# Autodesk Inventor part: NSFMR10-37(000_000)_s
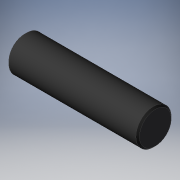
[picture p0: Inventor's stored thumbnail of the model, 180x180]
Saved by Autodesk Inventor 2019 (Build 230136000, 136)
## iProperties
Created: 2022-11
Part Number: NSFMR10-37(000_000)_s
Material: Generic
Catalog Web Link: www.cadenas.de
Description: NSFMR, SFMR, PSFMR, SSFMR, SSSFMR, NSFHR, SFHR, PSFHR, PPSFHR SSFHR, SSSFHR, NSFR, SFR, PSFR, PPSFR, SSFR, SSSFR, HFR, PHFR_shaft-Rotary Shafts - Straight -
Vendor: MISUMI
Document SubType Name: Modeling
Designer: psAdmin
Manufacturer: MISUMI
Mass: 2.89838 g
Surface Area: 13.0042 cm^2
Volume: 2.89838 cm^3
Density: 1 g/cm^3
Appearance: PSOLRGB-175-175-175
Category: PARTsolutions
Company: MISUMI
Title: NSFMR10-37
Author: Cadenas PARTsolutions
Comments: Rotary Shafts - Straight -
PSOL_IDENT_0: {$CADENAS_DATA/23d-libs/misumi/metric/11_rotary_shafts/11_components/psfr/psfr.prj},560 {VTYP=3D},{N
PSOL_IDENT_1: B=NSFMR10-37(000_000)_s},{LINA=NSFMR10-37},{NN=NSFMR, SFMR, PSFMR, SSFMR, SSSFMR, NSFHR, SFHR, PSFHR
PSOL_IDENT_2: , PPSFHR SSFHR, SSSFHR, NSFR, SFR, PSFR, PPSFR, SSFR, SSSFR, HFR, PHFR_shaft},{DATE=21.04.2022 07:40
PSOL_IDENT_3: :10},{GEOMDATE=27.07.2021 07:07:13},{VERSION=},{LINEID=30},{WBVAR=TS,MAT,ST,ALT1,L,ALT2,KC,A,WKC,C,K
PSOL_IDENT_4: ,E,KZ,Z,ALT3,FC,GALT3,WFC,J,WALT3,V,ALT4,SFC,SG,AG,ALT10,KWC,ALT11,WC,ALT6,TA,TB,ALT5,UC,ALT7,SC,ALT
PSOL_IDENT_5: 32,CD,ALT34,TCJ,WTCJ,XT,HCJ,WHCJ,XH},{WBNUMERIC=L,KC,A,WKC,C,K,E,KZ,Z,FC,GALT3,WFC,J,WALT3,V,SFC,SG,
PSOL_IDENT_6: AG,KWC,WC,TA,TB,UC,SC,TCJ,WTCJ,XT,HCJ,WHCJ,XH}  {NB=NSFMR10-37(000_000)_s},{LINA=NSFMR10-37},{KT=DUM
PSOL_IDENT_7: MY},{PN=NSFMR10-37},{TYPE=NSFMR},{TS=M},{TSALG= 'M','h9 (Cold-drawn)','H','h7 (Ground)','','g6 (Grou
PSOL_IDENT_8: nd)' },{MAT=S45C},{MATALG= 'S45C','S45C Equivalent', 'SUS304','304 Stainless Steel' },{ST=},{STALG= ''
PSOL_IDENT_9: ,'-','BO','Black Oxide', 'ENP','Electroless Nickel Plating' },{D=10.0},{ALT1=},{L=37.0},{LALG=[15:80
PSOL_IDENT_10: 0/0.1]},{LMIN=15},{LMAX=800},{NOTE=Not Applicable},{ALT2=},{ALT2ALG= '', 'w/o Key Grooves','KC','wit
PSOL_IDENT_11: h KC (Key Groove)','WKC','with WKC (Two Key Grooves)','KCWKC','with KC + WKC (Three Key Grooves)','K
PSOL_IDENT_12: Z','with KC + WKC + KZ (Four Key Grooves)' },{ALT2PN=},{KC=0.0},{KCALG=[0]},{KCMIN=0},{KCMAX=0},{A=0
PSOL_IDENT_13: .0},{AALG=[0]},{AMIN=3},{AMAX=0},{WKC=0.0},{WKCALG=[0]},{WKCMIN=0},{WKCMAX=0},{C=0.0},{CALG=[0]},{CM
PSOL_IDENT_14: IN=3},{CMAX=0},{K=0.0},{KALG=[0]},{KMIN=0},{KMAX=32},{E=0.0},{EALG=[0]},{EMIN=3},{EMAX=35},{KZ=0.0},
PSOL_IDENT_15: {KZALG=[0]},{KZMIN=39},{KZMAX=34},{Z=0.0},{ZALG=[0]},{ZMIN=3},{ZMAX=37},{CIFKC=1},{CIFWKC=1},{CIFK=1
PSOL_IDENT_16: },{CIFKZ=2},{PCUT3D=0.000},{QCUT3D=0},{BB=3},{BBALT2=3},{TT=1.8},{TTALT2=1.8},{ALT3=},{ALT3ALG= '', '
PSOL_IDENT_17: w/o Set Screw Flat','FC','with FC (Adds a Set Screw Flat)','WFC','with WFC (Adds Two Set Screw Flats
PSOL_IDENT_18: )','FCWFC','with FC + WFC (Adds Three Set Screw Flats)' },{ALT3PN=},{FC=0},{FCALG=[0]},{FCMIN=0},{FC
PSOL_IDENT_19: MAX=36},{GALT3=0},{GALT3ALG=[0]},{GALT3MIN=1},{GALT3MAX=37},{GALT3MAX2=31},{GALT3MAX3=34},{WFC=0},{W
PSOL_IDENT_20: FCALG=[0]},{WFCMIN=0},{WFCMIN2=2},{WFCMAX=33},{WFCMAX2=-3},{WFCMAX3=-4},{J=0},{JALG=[0]},{JMIN=1},{J
PSOL_IDENT_21: MAX=34},{JMAX2=-2},{JMAX3=-5},{WALT3=0},{WALT3ALG=[0]},{WALT3MIN=0},{WALT3MIN2=39},{WALT3MAX=34},{WA
PSOL_IDENT_22: LT3MAX2=34},{WALT3MAX3=34},{V=0},{VALG=[0]},{VMIN=1},{VMAX=35},{VMAX2=35},{VMAX3=35},{CIFFC=0},{ALT4=
PSOL_IDENT_23: },{ALT4ALG= '', 'w/o SFC (2 Set Screw Flats (Angle Specified))', 'SFC'  , 'with SFC (2 Set Screw Fla
PSOL_IDENT_24: ts (Angle Specified))'},{ALT4PN=},{SFC=0},{SFCALG=[0]},{SFCMIN=0},{SFCMAX=36},{SG=0},{SGALG=[0]},{SG
PSOL_IDENT_25: MIN=1},{SGMAX=37},{AG=0},{AGALG=[0]},{H=0.0},{CIFSFC=0},{ALT10=},{ALT10ALG= '', 'w/o KWC (2 Set Scre
PSOL_IDENT_26: w Flats at both ends)', 'KWC', 'with KWC (2 Set Screw Flats at both ends)' },{ALT10PN=},{KWC=0},{KWC
PSOL_IDENT_27: ALG=[0]},{KWCMIN=1},{KWCMAX=17.5},{WALT10=8},{ALT11=},{ALT11ALG= '','Not applicable' },{ALT11PN=},{W
PSOL_IDENT_28: C=0.0},{WCALG=[0]},{ALT6=},{ALT6ALG= '','w/o Retaining Ring Groove','TA','with TA (Retaining Ring Gr
PSOL_IDENT_29: oove)','TB','with TB (Retaining Ring Groove)','TATB','with TA + TB (Two Retaining Ring Grooves)' },{
PSOL_IDENT_30: ALT6PN=},{TA=0.0},{TAALG=[0]},{TAMIN=2},{TAMAX=0},{TB=0.0},{TBALG=[0]},{TBMIN=2},{TBMAX=0},{DDALT6=0
PSOL_IDENT_31: .0},{MM=0.00},{ALT5=},{ALT5ALG= '', 'w/o UC (Slit Cam Groove)', 'UC', 'with UC (Slit Cam Groove)'},{
PSOL_IDENT_32: ALT5PN=},{UC=0},{UCALG=[0]},{UCMIN=1},{UCMAX=31},{DDALT5=0},{LL1=0},{ALT7=},{ALT7ALG= '', 'w/o SC (W
PSOL_IDENT_33: rench Flats)', 'SC', 'with SC (Wrench Flats)'},{ALT7PN=},{SC=0},{SCALG=[0]},{SCMIN=0},{SCMAX=29},{WA
PSOL_IDENT_34: LT7=0},{LL2=0},{LL2ALG=8},{CIFSC=0},{ALT32=},{ALT32ALG=  '','w/o CD (Changes Part D Chamfering)','-C
PSOL_IDENT_35: D', 'with CD (Changes Part D Chamfering)' },{ALT32PN=},{CD=},{CDALG= '','N/A' },{CD3D=0.5},{CIF32=0}
PSOL_IDENT_36: ,{CIF320=0},{CIFTA=0},{CIFTB=0},{ERRORPN=},{ERRORALT23=OK},{ERRORALT24=OK},{ERRORALT25=OK},{ERRORALT
PSOL_IDENT_37: 26=OK},{ERRORALT27=OK},{ERRORALT210=OK},{ERRORALT34=OK},{ERRORALT35=OK},{ERRORALT36=OK},{ERRORALT37=
PSOL_IDENT_38: OK},{ERRORALT310=OK},{ERRORALT45=OK},{ERRORALT46=OK},{ERRORALT47=OK},{ERRORALT410=OK},{ERRORALT56=OK
PSOL_IDENT_39: },{ERRORALT57=OK},{ERRORALT510=OK},{ERRORALT610=OK},{ERRORALT75=OK},{ERRORALT76=OK},{ERRORALT710=OK}
PSOL_IDENT_40: ,{ALT34=},{ALT34ALG= '','Not applicable'},{TCJ=0},{WTCJ=0},{XT=0},{TM=4},{TCJALG=[0]},{TCJMIN=0.000}
PSOL_IDENT_41: ,{TCJMAX=15.000},{TCJMAX1=15.000},{HCJ=0},{WHCJ=0},{XH=0},{HP=4},{HCJALG=[0]},{HCJMIN=0.000},{HCJMAX=
PSOL_IDENT_42: 15.000},{HCJMAX1=15.000},{LCJ=0},{LMINX=15},{XCJMIN=4.000},{XALG=[0]},{XCJMAX=15.000},{WHCJMIN=0.000
PSOL_IDENT_43: },{WTCJMIN=0.000},{WTCJALG=[0]},{WHCJALG=[0]},{XHCJMIN=4.000},{XHALG=[0]}
NB: NSFMR10-37(000_000)_s
NN: NSFMR, SFMR, PSFMR, SSFMR, SSSFMR, NSFHR, SFHR, PSFHR, PPSFHR SSFHR, SSSFHR, NSFR, SFR, PSFR, PPSFR, SSFR, SSSFR, HFR, PHFR_shaft
NT: Rotary Shafts - Straight -
NBSYN: $PN.($ALT34.$TCJ.$WTCJ.$XT._$HCJ.$WHCJ.$XH.)_s
LINA: NSFMR10-37
CATALOG: Misumi
PN: NSFMR10-37
TS: h9 (Cold-drawn)
MAT: S45C Equivalent
ST: -
D: 10
ALT1: w/o LKC (Changes L Tolerance)
L: 37
ALT2: w/o Key Grooves
KC: 0
A: 0
WKC: 0
C: 0
K: 0
E: 0
KZ: 0
Z: 0
ALT3: w/o Set Screw Flat
FC: 0
GALT3: 0
WFC: 0
J: 0
WALT3: 0
V: 0
ALT4: w/o SFC (2 Set Screw Flats (Angle Specified))
SFC: 0
SG: 0
AG: 0
H: 0
ALT10: w/o KWC (2 Set Screw Flats at both ends)
KWC: 0
ALT11: Not applicable
WC: 0
ALT6: w/o Retaining Ring Groove
TA: 0
TB: 0
DDALT6: 0
MM: 0
ALT5: w/o UC (Slit Cam Groove)
UC: 0
DDALT5: 0
LL1: 0
ALT7: w/o SC (Wrench Flats)
SC: 0
WALT7: 0
LL2: 0
ALT32: w/o CD (Changes Part D Chamfering)
CD: N/A
ALT34: Not applicable
TCJ: 0
WTCJ: 0
XT: 0
HCJ: 0
WHCJ: 0
XH: 0
SUPPLIER: MISUMI
ARTICLENO: NSFMR10-37(000_000)_s
BOMINFO: NSFMR10-37
CREATOR: CADENAS GmbH
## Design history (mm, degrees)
sketch "Sketch_1"
  geometry: L1 (37, 0)-(0, 0); L2 (0, 0)-(0, 4.5); L3 (0, 4.5)-(0.5, 5); L4 (0.5, 5)-(36.5, 5); L5 (36.5, 5)-(37, 4.5); L6 (37, 4.5)-(37, 0); L7 (37, 0)-(0, 0)
  constraints: 14 end point
revolve "Revolution1" sketch "Sketch_1" stored, may be unused: angle "d0" = 360 deg
node "COMBINATION_MODULE_XY"
node "COMBINATION_MODULE_YZ"
node "COMBINATION_MODULE_ZX"
node "COMBINATION_MODULE_X"
node "COMBINATION_MODULE_Y"
node "COMBINATION_MODULE_Z"
node "COMBINATION_MODULE_Center"
body "Solid1"
other parameters: "d1" = 0
